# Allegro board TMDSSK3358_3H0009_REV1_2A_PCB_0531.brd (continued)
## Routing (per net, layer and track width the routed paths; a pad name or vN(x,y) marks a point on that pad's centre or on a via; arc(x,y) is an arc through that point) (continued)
DDR_BA2: length 43
  TOP w0.14: v2(77.12,11.96) 76.92,11.96 76.77,11.81 76.77,11.61 77.04,11.33 77.17,11.33 77.4,11.56 77.6,11.56 77.83,11.33 78.01,11.33 78.29,11.61 78.47,11.61 78.75,11.33 81.77,11.33 82.2,10.9 82.4,10.9 82.53,11.02 82.53,11.48 82.68,11.63 RP5.8
  LY6_SIG2 w0.127: v2(80.42,25.35) 81.21,24.56 81.43,24.56 83.48,22.52 83.48,19.12 84.28,18.31 84.28,13.57 80.83,10.12 78.63,10.12 78.29,9.78 78.29,8.59 77.29,7.59 76.36,7.59 76.21,7.44 75.34,7.44 75.12,7.66 75.12,8.16 75.36,8.4 75.68,8.4 75.91,8.63 75.91,9.89 76.29,10.27 76.29,11.14 v2(77.12,11.96)
  BOTTOM w0.14: U26.B3 79.91,27.44 79.91,25.85 v2(80.42,25.35) ; v2(77.12,11.96) 77.12,11.98 77.13,11.98 U32.M3
DDR_CASN: length 41.6
  TOP w0.14: v2(75.51,12.79) 75.51,12.48 76.97,11.02 81.64,11.02 82.12,10.54 RP6.1
  LY3_SIG1 w0.127: v2(76.34,25.4) 76.34,26.47 76.51,26.64 77.27,26.64 77.43,26.49 77.43,26.26 77.25,26.09 77.04,26.09 76.87,25.91 76.87,25.65 77.27,25.25 77.27,25.02 77.04,24.79 77.04,24.56 77.25,24.36 77.81,24.36 78.01,24.16 78.01,23.88 77.86,23.73 76.94,23.73 76.79,23.58 76.79,23.37 76.94,23.22 77.86,23.22 78.01,23.07 78.01,22.86 77.86,22.71 76.94,22.71 76.79,22.56 76.79,22.35 76.94,22.21 77.86,22.21 78.01,22.06 78.01,21.85 77.86,21.7 77.6,21.7 77.45,21.55 77.45,21.34 77.6,21.19 77.86,21.19 78.01,21.04 78.01,20.52 77.78,20.29 77.1,20.29 76.9,20.09 76.9,19.29 77.04,19.14 77.66,19.14 77.81,18.99 77.81,18.78 77.66,18.63 77.04,18.63 76.9,18.48 76.9,18.27 77.04,18.12 77.35,18.12 77.5,17.97 77.5,17.76 77.35,17.61 77.07,17.61 76.92,17.46 76.92,16.36 76.77,16.21 76.35,16.21 76.18,16.04 76.18,15.77 76.31,15.64 77.97,15.64 78.12,15.48 78.12,15.29 77.96,15.13 76.27,15.13 76.11,14.97 76.11,14.76 76.26,14.62 76.9,14.62 77.04,14.47 77.04,13.41 76.82,13.19 75.91,13.19 v2(75.51,12.79)
  BOTTOM w0.14: U32.K3 v2(75.51,12.79) ; v2(76.34,25.4) U26.F1
DDR_CKE: length 47
  LY3_SIG1 w0.127: v2(75.51,7.99) 75.92,8.4 79.66,8.4 79.91,8.16 79.91,7.83 79.67,7.59 79.35,7.59 74.71,7.59 74.31,7.99 74.31,8.96 73.97,9.3 73.97,9.63 74.25,9.91 74.25,11.68 75.11,12.55 75.11,13.94 75.64,14.46 75.64,17.63 76.33,18.32 76.33,24.03 76.49,24.18 76.49,24.7 76.18,25.01 76.18,25.01 75.94,25.24 v2(75.94,27.41)
  BOTTOM w0.14: v2(75.51,7.99) U32.K9 74.89,7.37 74.89,6.84 75.52,6.2 82.45,6.2 84.33,8.08 84.33,8.42 84.9,8.99 RP7.1 84.96,7.97 R242.2 ; U26.G3 v2(75.94,27.41)
DDR_CLK: length 41.1
  TOP w0.127: v2(74.71,9.6) 74.36,9.6 74.23,9.73 74.23,10.11 74.43,10.31 74.86,10.31 74.99,10.44 74.99,11.68 74.73,11.94 74.23,11.94 74.12,11.83 74.12,10.82 73.87,10.57 73.18,10.57 72.59,11.16 71.62,11.16 R89.1
  LY3_SIG1 w0.127: v2(81.36,23.11) 81.18,23.29 81.18,24.41 81.36,24.59 82.1,24.59 82.76,23.93 82.76,22.86 82.58,22.68 81.89,22.68 81.59,22.38 81.59,20.72 81.87,20.45 82.37,20.45 82.52,20.3 82.52,18.61 82.97,18.16 82.97,17.41 82.52,16.96 82.52,16.55 82.97,16.1 82.97,15.91 82.52,15.46 82.52,15.07 82.97,14.63 82.97,13.67 80.24,10.95 75.69,10.95 74.99,10.24 74.99,9.87 v2(74.71,9.6)
  BOTTOM w0.127: U26.D2 78.28,26.67 78.28,26.36 78.28,26.36 78.28,26.07 78.28,25.26 78.63,24.9 79.76,24.9 80.74,23.92 80.74,23.73 v2(81.36,23.11) ; U32.J7 v2(74.71,9.6)
DDR_CLKN: length 41.1
  TOP w0.127: R88.1 71.35,11.81 71.75,11.41 72.69,11.41 73.29,10.82 73.76,10.82 73.87,10.93 73.87,11.94 74.12,12.19 74.83,12.19 75.24,11.79 75.24,9.87 v2(75.51,9.6)
  LY3_SIG1 w0.127: v2(75.51,9.6) 75.24,9.87 75.24,10.13 75.8,10.69 76,10.69 76.26,10.44 76.51,10.44 76.77,10.69 80.35,10.69 83.22,13.56 83.22,14.73 82.77,15.18 82.77,15.35 83.22,15.8 83.22,16.2 82.77,16.65 82.77,16.85 83.22,17.3 83.22,18.26 82.77,18.71 82.77,20.41 82.48,20.7 81.97,20.7 81.85,20.83 81.85,22.28 82,22.43 82.68,22.43 83.01,22.76 83.01,24.03 82.2,24.84 81.26,24.84 80.93,24.51 80.93,23.32 v2(80.73,23.11)
  BOTTOM w0.127: v2(80.73,23.11) 80.49,23.35 80.49,23.81 79.65,24.65 78.53,24.65 77.95,25.23 77.95,26.2 U26.D1 ; U32.K7 v2(75.51,9.6)
DDR_CSN: length 43.5
  TOP w0.14: v2(76.31,13.6) 76.31,14.48 76.9,15.07 78.65,15.07 79.03,15.44 80.17,15.44 80.9,14.71 RP5.2
  LY6_SIG2 w0.127: v2(75.14,26.61) 74.33,26.61 73.96,26.98 73.96,27.53 73.69,27.8 73.38,27.8 73.15,28.03 73.15,28.37 72.9,28.62 72.58,28.62 72.34,28.86 72.34,31.66 72.12,31.87 71.78,31.87 71.54,31.64 71.54,29.9 71.87,29.57 71.87,28.84 72.34,28.37 72.34,28.05 72.58,27.82 72.73,27.82 72.73,27.82 72.89,27.82 72.9,27.81 72.9,27.81 73.16,27.55 73.16,26.73 73.37,26.52 73.77,26.52 73.96,26.34 73.96,26.1 73.78,25.92 72.94,25.92 72.73,25.7 72.73,25.17 72.89,25 73.37,25 73.52,24.86 73.52,24.19 73.67,24.04 73.84,24.04 74,23.88 74,23.52 73.54,23.05 73.54,22.32 73.67,22.19 73.91,22.19 74.12,22.41 74.12,22.92 74.29,23.09 75.15,23.09 75.36,22.89 75.36,22.39 74.4,21.44 74.4,18.72 75.31,17.81 75.45,17.67 75.45,16.42 76.05,15.82 76.05,15.34 76.31,15.08 v2(76.31,13.6)
  BOTTOM w0.14: U26.H2 v2(75.14,26.61) ; U32.L2 v2(76.31,13.6)
DDR_D0: length 29.8
  LY6_SIG2 w0.127: v2(71.14,27.41) 71.2,27.41 71.67,26.94 71.67,25.72 71.99,25.4 71.99,24.92 71.43,24.36 71.43,23.75 71.82,23.36 72.37,23.36 72.59,23.14 72.59,17.95 73.67,16.87 73.67,15.64 74.29,15.02 74.29,11.22 73.15,10.07 73.15,9.55 73.52,9.17 73.52,8.62 74.33,7.81 74.33,6.45 73.93,6.05 72.96,6.05 72.7,6.31 72.7,7.47 73.11,7.89 v2(73.11,8.8)
  BOTTOM w0.14: U26.M3 v2(71.14,27.41) ; U32.H8 v2(73.11,8.8)
DDR_D1: length 29.9
  LY6_SIG2 w0.127: v2(73.81,10.08) 73.81,9.44 73.99,9.26 74.17,9.26 74.32,9.41 74.32,9.87 74.52,10.08 74.88,10.08 75.07,10.27 75.07,10.52 74.91,10.69 74.78,10.69 74.63,10.83 74.63,11.04 74.79,11.19 75.36,11.19 75.5,11.34 75.5,11.55 75.35,11.7 74.82,11.7 74.67,11.85 74.67,12.06 74.83,12.21 74.97,12.21 75.11,12.36 75.11,14.92 74.54,15.49 74.32,15.71 74.18,15.85 74.18,16.69 74.18,17.08 73.13,18.13 73.13,18.19 73.13,19.25 73.13,19.25 73.13,24.05 72.33,24.85 72.33,25.57 72.1,25.79 72.1,26.98 72.33,27.2 72.33,27.58 72.1,27.81 72.08,27.81 72.07,27.82 70.89,27.82 70.74,27.96 70.74,29.18 70.99,29.42 71.33,29.42 71.54,29.2 71.54,28.61 v2(71.14,28.21)
  BOTTOM w0.14: U32.H7 73.51,9.8 73.8,10.08 v2(73.81,10.08) ; U26.M4 v2(71.14,28.21)
DDR_D2: length 29.7
  LY6_SIG2 w0.127: v2(70.74,25.27) 70.74,22.69 71.1,22.33 71.31,22.33 71.45,22.18 71.45,21.97 71.31,21.82 71.11,21.82 70.96,21.67 70.96,21.41 71.08,21.29 71.31,21.29 71.45,21.14 71.45,20.93 71.31,20.79 71.11,20.79 70.96,20.64 70.96,20.43 71.11,20.28 71.31,20.28 71.45,20.13 71.45,19.92 71.31,19.77 71.11,19.77 70.96,19.62 70.96,19.41 71.11,19.26 71.31,19.26 71.45,19.11 71.45,18.9 71.31,18.75 71.11,18.75 70.96,18.6 70.96,18.39 71.11,18.25 71.28,18.25 71.43,18.1 71.43,17.89 71.28,17.74 71.11,17.74 70.96,17.59 70.96,16.96 70.96,16.96 70.96,16.29 71.11,16.14 72.48,16.14 72.62,16 72.62,15.79 72.48,15.64 71.11,15.64 70.82,15.35 70.82,14.78 71.14,14.47 71.48,14.47 71.62,14.62 71.62,15.01 71.77,15.16 71.98,15.16 72.13,15.01 72.13,14.62 72.32,14.43 72.51,14.43 72.9,14.82 73.25,14.82 73.52,14.55 73.52,14.16 73.35,13.99 72.89,13.99 72.71,13.81 72.71,13.25 72.53,13.07 71.53,13.07 71.2,12.74 71.2,12.43 71.4,12.24 72.89,12.24 73.14,11.99 73.35,11.99 73.48,12.11 73.48,12.43 v2(73.11,12.79)
  BOTTOM w0.14: v2(70.74,25.27) U26.N1 ; U32.H3 v2(73.11,12.79)
DDR_D3: length 29.9
  LY6_SIG2 w0.127: v2(69.65,23.67) 69.65,23.32 67.77,21.44 67.77,21.23 67.94,21.06 67.94,20.85 67.79,20.7 67.58,20.7 67.41,20.87 67.2,20.87 67.05,20.72 67.05,20.51 67.67,19.89 67.67,19.68 67.53,19.53 67.31,19.53 66.69,20.15 66.48,20.15 66.3,19.97 66.3,18.89 66.43,18.76 67.62,18.76 67.76,18.62 67.76,18.41 67.62,18.26 66.43,18.26 66.3,18.13 66.3,17.72 67.13,16.88 67.62,16.88 67.77,16.74 67.77,16.53 67.62,16.38 67.2,16.38 67.05,16.23 67.05,16.02 67.2,15.87 67.62,15.87 67.77,15.72 67.77,15.51 67.62,15.36 67.2,15.36 67.05,15.21 67.05,14.59 67.26,14.38 67.88,14.38 68.03,14.23 68.03,14.02 67.88,13.87 67.16,13.87 67.01,13.72 67.01,13.41 68.24,12.18 70.1,12.18 v2(70.71,12.79)
  BOTTOM w0.102: U26.N2 70.35,26.62 70.35,24.37 v2(69.65,23.67)
  BOTTOM w0.14: v2(70.71,12.79) U32.E3
DDR_D4: length 29.8
  LY6_SIG2 w0.127: v2(70.34,27.41) 70.34,25.09 70.44,24.99 70.44,20.39 70.3,20.26 69.1,20.26 68.96,20.11 68.96,19.9 69.11,19.75 70.3,19.75 70.45,19.6 70.45,19.39 70.3,19.24 69.02,19.24 68.9,19.12 68.9,18.91 69.08,18.73 70.3,18.73 70.45,18.58 70.45,18.37 70.3,18.22 69.02,18.22 68.9,18.1 68.9,17.89 69.08,17.72 70.3,17.72 70.45,17.57 70.45,17.31 70.28,17.14 69.82,17.14 69.62,16.94 69.62,16.25 69.24,15.87 69.24,14.25 69.47,14.02 69.7,14.02 69.85,14.17 69.85,15.64 70,15.79 70.21,15.79 70.35,15.64 70.35,14.17 70.5,14.02 71.89,14.02 v2(72.31,13.6)
  BOTTOM w0.14: U32.G2 v2(72.31,13.6) ; U26.N3 v2(70.34,27.41)
DDR_D5: length 29.7
  LY6_SIG2 w0.127: v2(70.34,28.21) 70.34,28.78 70.08,29.03 70.08,29.36 70.72,30 70.72,31.29 70.59,31.42 70.16,31.42 69.75,31.01 69.38,31.01 69.15,30.78 69.15,30.76 69.14,30.76 69.14,28.85 69.38,28.62 69.69,28.62 69.93,28.38 69.93,28.32 69.93,26.82 70.06,26.7 70.06,22.73 69.27,21.94 69.27,21.73 69.67,21.33 69.67,21.12 69.52,20.98 69.31,20.98 68.91,21.37 68.7,21.37 68.5,21.17 68.5,20.66 68.3,20.46 68.3,15.12 68.71,14.7 68.71,13.43 68.7,13.43 68.93,13.2 71.12,13.2 v2(71.51,13.6)
  BOTTOM w0.14: U32.F2 v2(71.51,13.6) ; U26.N4 v2(70.34,28.21)
DDR_D6: length 29.7
  LY6_SIG2 w0.127: v2(69.54,27.41) 69.54,26.85 68.14,25.45 68.14,24.69 63.07,19.63 63.07,13.93 66.14,10.87 66.81,10.87 67.81,9.87 70.18,9.87 70.62,10.31 71.79,10.31 72.19,9.91 72.19,9.53 71.99,9.32 71.79,9.32 v2(71.51,9.6)
  BOTTOM w0.14: U32.F7 v2(71.51,9.6) ; U26.P3 v2(69.54,27.41)
DDR_D7: length 30
  LY6_SIG2 w0.127: v2(69.54,28.21) 69.14,27.82 69.14,27.18 67.73,25.76 67.73,25 62.57,19.84 62.57,13.51 66.77,9.31 69.5,9.31 70.81,7.99 v2(71.51,7.99)
  BOTTOM w0.14: U32.F8 v2(71.51,7.99) ; U26.P4 v2(69.54,28.21)
DDR_D8: length 29.8
  LY3_SIG1 w0.127: v2(69.11,12.79) 69.11,11.77 70.35,10.53 70.35,10.16 69.73,9.55 69.73,8.64 69.34,8.25 69.34,7.86 69.73,7.47 72.62,7.47 73.52,8.36 73.52,9.06 73.38,9.2 73.38,10.26 73.89,10.77 73.89,15.19 73.82,15.27 73.82,18.54 74.49,19.21 74.49,24.85 v2(73.94,25.4)
  BOTTOM w0.14: v2(73.94,25.4) U26.J1 ; U32.C3 v2(69.11,12.79)
DDR_D9: length 30.2
  LY3_SIG1 w0.127: v2(73.14,25.4) 72.64,25.4 71.23,23.99 71.23,22.16 70.94,21.87 70.94,20.45 71.18,20.2 71.18,19.85 71.03,19.7 70.82,19.7 70.57,19.95 70.36,19.95 70.21,19.8 70.21,19.59 70.46,19.34 70.46,19.13 70.31,18.98 70.1,18.98 69.85,19.23 69.64,19.23 69.49,19.08 69.49,18.87 69.74,18.62 69.74,18.41 69.5,18.17 68.49,18.17 66.76,16.43 66.76,14.4 66.62,14.27 66.02,14.27 65.87,14.12 65.87,13.91 66.02,13.76 66.62,13.76 66.77,13.61 66.77,13.4 66.62,13.25 66.02,13.25 65.87,13.11 65.87,12.89 66.02,12.75 66.62,12.75 66.76,12.61 66.76,11.91 67.67,11 67.67,10.7 67.49,10.51 67.21,10.51 v1(65.32,12.39)
  BOTTOM w0.14: v1(65.32,12.39) U32.A3 ; v2(73.14,25.4) U26.K1
DDR_D10: length 30.2
  LY3_SIG1 w0.127: v2(72.74,26.61) 72.74,25.89 70.8,23.95 70.8,22.96 69.4,21.56 69.4,20.79 69.79,20.39 69.79,20.18 69.64,20.04 69.43,20.04 68.97,20.49 68.76,20.49 68.61,20.35 68.61,20.13 69.07,19.68 69.07,19.47 68.92,19.32 68.71,19.32 68.25,19.78 68.04,19.78 67.9,19.63 67.9,19.42 68.35,18.96 68.35,18.75 68.21,18.6 68,18.6 67.54,19.06 67.33,19.06 67.18,18.91 67.18,18.7 67.64,18.24 67.64,18.03 67.49,17.88 67.28,17.88 66.82,18.34 66.61,18.34 66.46,18.19 66.46,17.98 66.92,17.52 66.92,17.31 66.77,17.16 66.56,17.16 66.1,17.62 65.89,17.62 65.32,17.05 65.32,16.75 65.47,16.6 66.1,16.6 66.25,16.45 66.25,16.24 66.1,16.09 65.47,16.09 65.32,15.95 65.32,15.74 65.47,15.59 66.1,15.59 66.25,15.44 66.25,15.23 66.1,15.08 65.47,15.08 65.32,14.93 v1(65.32,13.46)
  BOTTOM w0.14: v1(65.32,13.46) 66.48,13.46 66.75,13.2 U32.A2 ; U26.K2 v2(72.74,26.61)
DDR_D11: length 29.9
  LY3_SIG1 w0.127: v2(72.74,27.41) 72.24,26.92 72.24,26.46 71.53,25.74 70.53,25.74 70.16,25.37 70.16,25.17 69.12,24.13 68.5,24.13 65.58,21.21 64.95,20.58 64.95,19.9 65.11,19.74 65.33,19.74 65.54,19.53 65.54,19.14 63.76,17.36 63.76,12.34 66.45,9.65 69.17,9.65 v2(69.91,10.4)
  BOTTOM w0.14: U32.D7 69.91,9.6 v2(69.91,10.4) ; U26.K3 v2(72.74,27.41)
DDR_D12: length 30.3
  LY3_SIG1 w0.127: v2(72.74,28.21) 72.74,28 73.53,27.21 73.53,25.56 73.53,25.56 73.53,25.24 73.53,25.03 73.34,24.84 73.34,19.49 72.7,18.85 72.7,18.39 71.9,17.59 71.9,16.57 72.72,15.75 72.72,12.49 72.52,12.28 72.18,12.28 71.96,12.5 71.96,12.95 71.73,13.18 71.45,13.18 71.22,12.95 71.22,11.83 71.66,11.39 72.56,11.39 72.76,11.19 72.76,10.99 72.56,10.79 72.04,10.79 71.91,10.66 71.91,10.33 71.74,10.16 71.41,10.16 71.18,10.39 71.18,11.01 70.32,11.87 70.32,12.95 70.08,13.19 69.75,13.19 69.75,13.19 69.52,13.19 v2(69.11,13.6)
  BOTTOM w0.14: U32.C2 v2(69.11,13.6) ; U26.K4 v2(72.74,28.21)
DDR_D13: length 29.9
  LY3_SIG1 w0.127: v2(71.94,27.41) 71.62,27.09 71.62,26.39 71.35,26.13 69.63,26.13 69.1,25.6 69.1,24.85 68.83,24.58 68.23,24.58 63.26,19.6 63.26,19.28 63.4,19.13 64.23,19.13 64.37,18.99 64.37,18.78 64.22,18.62 63.4,18.62 63.26,18.47 63.26,12.13 66.81,8.57 67.5,8.57 67.72,8.8 v2(68.31,8.8)
  BOTTOM w0.14: U32.B8 v2(68.31,8.8) ; U26.L3 v2(71.94,27.41)
DDR_D14: length 30.3
  LY3_SIG1 w0.127: v2(71.94,28.21) 71.54,27.82 70.99,27.82 70.74,27.58 70.74,27.15 70.21,26.62 69.55,26.62 62.66,19.72 62.66,11.94 66.44,8.16 68.47,8.16 v2(69.11,8.8)
  BOTTOM w0.14: U32.C8 v2(69.11,8.8) ; U26.L4 v2(71.94,28.21)
DDR_D15: length 30.4
  LY3_SIG1 w0.127: v2(71.54,25.27) 71,24.74 70.5,24.74 70.15,24.39 70.15,23.31 69.51,22.67 69.3,22.67 68.62,23.34 68.43,23.34 68.28,23.19 68.28,22.97 68.94,22.31 68.94,22.1 68.79,21.95 68.58,21.95 67.9,22.62 67.71,22.62 67.56,22.47 67.56,22.25 68.22,21.59 68.22,21.38 68.07,21.23 67.86,21.23 67.19,21.9 66.99,21.9 66.84,21.76 66.84,21.53 67.5,20.87 67.5,20.66 67.35,20.51 67.14,20.51 66.52,21.13 66.3,21.13 66.15,20.98 66.15,20.79 66.78,20.15 66.78,19.66 64.82,17.69 64.82,12.08 v1(66.58,10.32)
  BOTTOM w0.14: U32.A7 66.96,9.2 66.58,9.57 v1(66.58,10.32) ; v2(71.54,25.27) U26.M1
DDR_DQM0: length 29.9
  LY6_SIG2 w0.127: v2(71.14,26.61) 71.15,26.6 71.15,23.48 71.96,22.66 71.96,17.86 73.16,16.66 73.16,15.47 73.9,14.73 73.9,11.4 72.71,10.21 72.71,8.17 72.29,7.76 72.29,6.92 71.71,6.34 70.51,6.34 70.22,6.62 70.22,7.22 70.46,7.46 71.62,7.46 71.91,7.75 71.91,7.83 71.91,7.83 71.91,8.16 71.91,8.16 71.91,8.4 v2(70.71,9.6)
  BOTTOM w0.14: U32.E7 v2(70.71,9.6) ; U26.M2 v2(71.14,26.61)
DDR_DQM1: length 30.1
  LY3_SIG1 w0.127: v2(73.94,24.57) 73.94,19.38 73.31,18.75 73.31,14.97 73.54,14.74 73.54,10.9 72.72,10.08 72.72,8.25 72.45,7.98 72.09,7.98 71.84,8.23 71.84,8.56 71.61,8.79 71.41,8.79 71.11,8.5 71.11,8.17 70.9,7.95 70.52,7.95 70.29,8.18 70.29,8.92 70.32,8.95 70.32,8.96 70.55,9.19 70.56,9.19 70.57,9.2 70.88,9.2 71.11,9.43 71.11,9.87 70.77,10.21 70.77,10.73 69.55,11.95 69.55,12.43 v2(69.91,12.79)
  BOTTOM w0.102: U26.J2 74.41,26.54 74.41,25.04 v2(73.94,24.57)
  BOTTOM w0.14: U32.D3 v2(69.91,12.79)
DDR_DQS0: length 30.3
  LY6_SIG2 w0.127: v2(71.91,11.81) 72.19,11.53 72.19,11.37 72.06,11.25 67.63,11.25 66.07,12.8 66.07,15.04 65.74,15.37 65.3,15.37 65.06,15.61 65.06,15.82 65.2,15.97 65.77,15.97 66.07,16.27 66.07,16.82 65.66,17.23 64.32,17.23 64.17,17.38 64.17,17.59 64.32,17.74 64.96,17.74 65.26,18.04 65.26,18.46 64.96,18.76 64.26,18.76 64.12,18.9 64.12,19.22 68.89,23.99 68.89,24.66 69.03,24.8 69.03,25.62 69.22,25.82 69.51,25.82 69.7,25.63 69.7,25.3 v2(69.51,25.1)
  BOTTOM w0.127: v2(71.91,11.81) U32.F3 ; v2(69.51,25.1) 69.94,25.53 U26.P1
DDR_DQS1: length 30.3
  LY3_SIG1 w0.127: v2(69.11,10.4) 68.82,10.69 68.82,11.14 67.56,12.39 67.56,13.83 67.75,14.02 71.64,14.02 72.02,14.4 72.02,15.36 71.3,16.08 69.94,16.08 69.02,15.16 68.46,15.16 68.04,15.58 68.04,16.28 68.91,17.15 69.71,17.15 69.71,17.15 69.92,17.15 72.2,19.43 72.2,20.63 72.09,20.73 72.09,23.37 72.19,23.47 72.43,23.47 72.56,23.33 72.81,23.33 72.93,23.46 72.93,23.7 v2(72.68,23.95)
  BOTTOM w0.127: v2(72.68,23.95) 72.68,23.98 72.38,24.27 72.38,25.74 72.34,25.78 U26.L1 ; v2(69.11,10.4) 68.89,10.17 68.89,9.9 69.24,9.55 69.24,9.32 69.37,9.2 U32.C7
DDR_DQSN0: length 30.3
  LY6_SIG2 w0.127: v2(68.63,25.05) 68.63,24.1 63.86,19.33 63.86,18.8 64.16,18.5 64.86,18.5 65,18.35 65,18.14 64.86,17.99 64.21,17.99 63.91,17.7 63.91,17.28 64.21,16.98 65.55,16.98 65.82,16.71 65.82,16.37 65.67,16.22 65.1,16.22 64.8,15.93 64.8,15.51 65.19,15.11 65.64,15.11 65.82,14.93 65.82,12.7 67.52,10.99 72.17,10.99 72.44,11.27 72.44,11.53 v2(72.71,11.81)
  BOTTOM w0.127: U32.G3 v2(72.71,11.81) ; v2(68.63,25.05) 69.55,25.97 69.55,26.66 69.9,27.01 U26.P2
DDR_DQSN1: length 30.3
  LY3_SIG1 w0.127: v2(71.84,23.98) 71.84,20.63 71.94,20.52 71.94,19.53 69.81,17.4 68.81,17.4 67.78,16.38 67.78,15.47 68.35,14.9 69.12,14.9 70.05,15.82 71.2,15.82 71.76,15.26 71.76,14.51 71.53,14.27 67.65,14.27 67.31,13.94 67.31,12.29 67.4,12.2 68.57,11.03 68.57,10.65 v2(68.31,10.4)
  BOTTOM w0.127: v2(71.84,23.98) 72.13,24.27 72.13,25.58 71.99,25.72 71.99,26.66 U26.L2 ; v2(68.31,10.4) 68.64,10.07 68.64,9.8 68.99,9.45 68.99,9.32 68.86,9.2 U32.B7
DDR_ODT: length 42
  TOP w0.14: RP5.1 80.93,15.29 80.27,15.95 79.05,15.95 78.54,15.44 75.62,15.44 v2(74.69,14.51)
  LY3_SIG1 w0.127: v2(75.54,25.5) 75.54,26.81 75.33,27.02 74.98,27.02 74.75,27.25 74.75,28.89 75.52,29.66 75.52,30.4 75.29,30.63 74.91,30.63 74.73,30.45 74.73,29.65 74.49,29.41 74.12,29.41 73.88,29.65 73.88,30.1 73.76,30.22 72.55,30.22 72.16,30.61 71.73,30.61 71.54,30.42 71.54,29.25 71.74,29.05 72.08,29.05 72.44,29.41 73.37,29.41 73.95,28.83 73.95,28.04 74.38,27.61 74.38,26.03 75.52,24.89 75.52,24.09 75.83,23.79 75.83,18.66 75.11,17.95 75.11,14.93 v2(74.69,14.51)
  BOTTOM w0.14: v2(74.69,14.51) 75.11,14.08 U32.K1 ; U26.G1 v2(75.54,25.5)
DDR_RASN: length 42.5
  TOP w0.14: RP6.2 82.25,9.96 81.51,10.69 76.82,10.69 v2(74.71,12.79)
  LY3_SIG1 w0.127: v2(74.71,12.79) 74.29,13.22 74.29,14.89 74.58,15.18 74.58,18.22 75.28,18.92 75.28,23.47 74.93,23.82 74.93,24.98 74.02,25.89 74.02,27.48 73.7,27.8 73.38,27.8 73.15,28.03 73.15,28.5 73.03,28.62 70.7,28.62 70.24,29.08 70.24,30.68 70.57,31.02 76.13,31.02 76.34,30.8 76.34,29.6 76.16,29.42 75.78,29.42 75.52,29.16 75.52,28.63 v2(75.94,28.21)
  BOTTOM w0.14: v2(75.94,28.21) U26.G4 ; U32.J3 v2(74.71,12.79)
DDR_RESETN: length 45.5
  LY6_SIG2 w0.127: v2(76.04,24.59) 76.04,24.37 75.88,24.21 75.71,24.21 75.57,24.35 75.57,24.85 75.93,25.22 75.93,25.55 76.29,25.91 76.56,25.91 76.75,25.71 76.75,24.55 76.46,24.25 76.46,23.98 76.69,23.75 76.69,21.43 76.03,20.78 76.03,19.25 76.16,19.13 76.51,19.13 76.64,19.26 76.64,20.29 76.74,20.4 77.07,20.4 77.16,20.31 77.16,17.54 77.31,17.39 77.57,17.39 77.7,17.51 77.7,19.43 77.85,19.58 78.06,19.58 78.21,19.43 78.21,17.94 78.35,17.79 79,17.79 79.15,17.64 79.15,17.43 79,17.28 78.14,17.28 77.94,17.08 77.94,16.45 78.11,16.28 78.46,16.28 78.6,16.14 78.6,15.84 78.46,15.7 78.01,15.7 77.7,15.39 77.7,14.61 77.86,14.45 78.09,14.45 78.21,14.58 78.21,15.08 78.34,15.2 78.57,15.2 78.7,15.07 78.7,14.2 78.9,13.99 79.74,13.99 79.86,13.87 80.38,13.87 v2(80.41,13.9)
  BOTTOM w0.102: v2(76.04,24.59) 76.04,25.11 75.93,25.22 75.93,26.62 U26.G2 ; v2(80.41,13.9) 80.42,13.91 80.42,13.91
  BOTTOM w0.14: 80.42,13.91 79.91,13.4 U32.T2 ; v2(80.41,13.9) 80.41,15.05 80.88,15.52 83.41,15.52 83.83,15.95 83.83,16.84 83.96,16.96 84.34,16.96 84.47,16.84 84.47,14.27 R241.1 85.36,14.56 R237.2
DDR_VREF: length 115.8
  TOP w0.254: C187.1 91.42,2.3 U14.6
  TOP w0.381: 80.07,0.96 80.1,0.94 85.36,0.94 85.69,1.27 v1(85.69,1.93) 85.75,1.87 86.23,1.87 86.24,1.88 87.22,0.89 91.82,0.89 C187.1 ; v2(73.11,14.39) 73.58,14.86 C145.1 ; C125.1 74.4,28.15 v2(74.34,28.21)
  TOP w0.508: v2(77.11,7.99) 76.71,7.99 76.41,7.7 76.41,6.96 76.84,6.53
  TOP w0.635: 76.84,6.53 76.84,5.89 ; 76.84,5.89 76.84,5.79 77.66,4.97 77.66,2.05 78.75,0.96 80.07,0.96 ; 76.84,5.89 75.83,4.88 68.46,4.88 65.91,7.43 65.91,11.32 66.63,12.04 66.63,12.91 67.55,13.83 67.59,13.87 67.68,13.92 67.72,13.94 68.33,14.55 69.37,14.55 69.66,14.84 72.66,14.84 v2(73.11,14.39) ; v1(97.67,22.63) 97.66,22.64 v1(97.66,23.37) 97.66,24.26 95.61,26.31 94.51,26.31 92.18,23.98 87.53,23.98 87.45,24.05 80.74,24.05 79.47,22.78 78.37,22.78 77.73,23.42 76.08,23.42 74.86,24.64 74.86,25.55 74.4,26.01 C125.1
  BOTTOM w0.305: U26.J4 v2(74.34,28.21)
  BOTTOM w0.381: 73.4,14.9 73.11,14.62 v2(73.11,14.39) U32.H1 ; U32.M8 v2(77.11,7.99) ; v1(85.69,1.93) 85.69,2.38 85.47,2.6 TP25.1
  BOTTOM w0.635: v1(97.66,23.37) 97.67,23.36 v1(97.67,22.63) 96.81,21.77 89.45,21.77 87.97,20.29 87.97,20.17 87.25,19.44 79.87,19.44 78.49,18.06 75.52,18.06 73.83,16.37 73.83,15.34 73.4,14.9
DDR_VTT_EN: length 3.3
  TOP w0.14: v1(91.54,2.8) U14.7
  BOTTOM w0.14: R243.2 R245.1 91.07,3.25 91.52,2.8 v1(91.54,2.8)
DDR_WEN: length 41.7
  TOP w0.14: v2(76.31,12.79) 76.05,12.79 75.95,12.69 75.95,12.55 76.36,12.14 76.61,12.14 76.87,12.4 78.17,12.4 78.47,12.7 80.85,12.7 81.13,12.42 81.82,12.42 82.11,12.71 RP5.6
  LY3_SIG1 w0.127: v2(79.14,27.41) 78.93,27.41 78.52,27 78.04,27 77.81,26.77 77.81,26.14 77.96,25.98 77.96,24.76 78.14,24.58 79.05,24.58 79.23,24.4 79.23,24.07 78.79,23.63 78.57,23.63 78.35,23.41 78.35,23.03 78.49,22.88 79.13,22.88 79.28,22.73 79.28,22.52 79.13,22.37 78.72,22.37 78.57,22.22 78.57,22.01 78.72,21.87 79.64,21.87 79.79,21.71 79.79,21.46 79.69,21.36 78.67,21.36 78.52,21.21 78.52,21 78.67,20.85 79.59,20.85 79.74,20.7 79.74,20.49 79.59,20.34 78.55,20.34 78.33,20.12 78.33,19.85 78.45,19.72 78.65,19.72 78.81,19.56 78.81,18.79 78.63,18.61 78.46,18.61 78.15,18.3 78.15,17.71 77.96,17.51 77.96,16.64 78.65,15.94 78.65,15.22 78.39,14.97 78.39,14.67 78.71,14.35 78.71,14.16 78.59,14.04 77.72,14.04 77.52,13.85 77.52,12.69 77.22,12.4 76.84,12.4 76.66,12.22 76.66,11.66 76.51,11.51 75.7,11.51 75.02,10.83 74.81,10.83 74.63,11.01 74.63,11.45 75.45,12.27 76.13,12.27 76.31,12.46 v2(76.31,12.79)
  BOTTOM w0.14: U26.B2 v2(79.14,27.41) ; U32.L3 v2(76.31,12.79)
DISEN: length 3.4
  TOP w0.14: J1.31 46.31,35.04 47.26,35.99 RP4.10
EMU2: length 5.8
  BOTTOM w0.14: J12.17 93.55,5.85 92.47,6.93 TP20.1
EMU3: length 7.7
  BOTTOM w0.14: J12.18 93.55,11.01 v1(93.43,11.12) 92.8,11.76 90.44,11.76 89.42,10.74 TP18.1
EMU4: length 5.5
  BOTTOM w0.14: J12.19 92.28,5.47 91.96,5.79 91.07,5.79 90.69,6.17 89.68,6.17 TP22.1
EMU_RSTN: length 6
  TOP w0.14: v1(95.47,1.98) 97.63,1.98 97.75,1.85 97.88,1.85 C183.1
  BOTTOM w0.14: J12.15 94.82,2.63 v1(95.47,1.98)
ETH1_INTN: length 7.8
  BOTTOM w0.14: R124.1 R123.2 R122.1 97.47,47 95.41,44.95 U23.5
ETH1_RBIAS: length 5.7
  BOTTOM w0.14: U23.9 97.01,43.95 97.45,44.39 97.45,44.39 98.03,44.98 100.26,44.98 100.53,44.7 R146.2
ETH1_RXCLK: length 5.5
  BOTTOM w0.14: U23.33 95.01,35.68 94.45,35.12 94.22,35.12 93.53,34.43 R209.2 93.89,33.04 93.97,33.04 R208.1
ETH1_RXD0: length 6.4
  BOTTOM w0.14: R204.1 98.86,33.4 98.79,33.47 98.31,33.47 98.24,33.4 R205.2 97.5,33.94 96.16,33.94 95.56,34.55 95.56,35.3 95.67,35.41 95.67,35.43 95.81,35.57 U23.31
ETH1_RXD1: length 8
  BOTTOM w0.14: U23.30 96.21,35.91 96.15,35.85 96.15,35.44 95.97,35.27 95.97,34.87 96.38,34.46 99.27,34.46 R203.1 R202.2
ETH1_RXD2: length 4.8
  TOP w0.14: v1(97.34,35.05) 98.04,34.35 R68.2 R69.1
  BOTTOM w0.14: U23.28 97.01,35.99 97.34,35.67 v1(97.34,35.05)
ETH1_RXD3: length 7
  TOP w0.14: R71.1 R70.2 99.88,34.99 v1(99.13,34.99)
  BOTTOM w0.14: v1(99.13,34.99) 98.3,34.99 97.8,35.48 97.8,35.67 97.41,36.06 U23.27
ETH1_RXDV: length 4.9
  BOTTOM w0.14: U23.32 95.41,35.64 95.34,35.57 95.34,35.55 95.04,35.24 95.04,34.05 R207.2 95.99,33.4 96,33.41 96.43,33.41 96.62,33.4 R206.1
ETH2_INTN: length 10.7
  TOP w0.14: v1(54.67,45.06) 54.29,45.06 54.29,45.06 51.93,45.06 51.55,45.44 51.55,47.34 51.37,47.53 R22.1 R21.1 R20.1
  BOTTOM w0.14: v1(54.67,45.06) 55.03,44.7 U24.5
ETH2_RBIAS: length 3.8
  BOTTOM w0.14: U24.9 56.63,43.38 56.55,43.46 56.55,44.38 57.13,44.96 R145.2
ETH2_RXCLK: length 5.5
  BOTTOM w0.14: U24.33 54.63,35.11 54.1,34.59 53.71,34.59 53.71,34.59 53.55,34.43 53.08,34.43 52.38,33.74 R199.2 R200.1
ETH2_RXD0: length 4.2
  BOTTOM w0.14: R195.1 R196.2 55.64,33.87 55.64,34.54 55.42,34.76 55.42,36.08 55.43,36.09 U24.31
ETH2_RXD1: length 4.9
  BOTTOM w0.14: U24.30 55.83,36.09 55.75,36.01 55.75,35.16 56.48,34.43 56.77,34.43 57.46,33.73 R194.1 R193.2
ETH2_RXD2: length 4.4
  TOP w0.14: v1(56.64,34.94) 56.13,34.43 R64.2 R65.1
  BOTTOM w0.14: U24.28 56.63,36.14 56.7,36.07 56.7,35.62 56.64,35.56 v1(56.64,34.94)
ETH2_RXD3: length 6.1
  TOP w0.14: v1(57.4,34.92) 57.4,34.29 58.04,33.66 R66.2 R67.1
  BOTTOM w0.14: v1(57.4,34.92) 57.4,35.59 57.03,35.96 57.03,36.15 57.03,36.15 U24.27
ETH2_RXDV: length 4.3
  BOTTOM w0.14: U24.32 55.03,34.98 54.41,34.36 R197.1 R198.2
ETH_MDIO_CLK: length 2.6
  BOTTOM w0.14: R147.1 52.25,43.43 52.86,42.83 U24.1
ETH_MDIO_DATA: length 3.4
  BOTTOM w0.14: U24.48 52.55,42.38 52.13,42.8 50.58,42.8 50.04,43.34 R148.1
ETH_RESETN: length 91.3
  TOP w0.14: v1(88.58,48.87) 84.64,48.87 84.16,48.39 84.16,47.32 84.99,46.48 84.99,45.69 85.35,45.34 U6.4 ; R47.1 v1(51.87,43.91) 48.19,47.59 v1(48.19,50.7) ; v1(93.6,45.34) 94.74,46.48 R26.2
  LY3_SIG1 w0.127: v1(48.19,50.7) 48.19,52.37 50.92,55.1 68.31,55.1 69.19,54.22 69.19,53.31 69.48,53.02 77.62,53.02 79.36,54.77 88.07,54.77 88.6,54.24 88.6,53.76 90.16,52.2 93.52,52.2 94.14,51.57 94.14,45.88 v1(93.6,45.34) 93.18,45.76 92.63,45.76 91.56,46.82 90.63,46.82 v1(88.58,48.87)
  BOTTOM w0.14: U23.2 94.21,43.33 93.4,44.14 93.4,45.14 v1(93.6,45.34) ; v1(51.87,43.91) 52.54,43.91 52.89,43.56 53.59,43.56 53.83,43.33 U24.2
ETHER2_D0N: length 22.9
  LY6_SIG2 w0.121: v1(57.96,44.39) 57.74,44.17 57.74,42.82 58.86,41.7 60.91,41.7 62.6,43.39 62.6,47.47 63.03,47.9 63.03,48.47 64.22,49.66 64.78,49.66 65.69,50.57 65.69,51.99 66.52,52.82 66.95,52.82 68,53.87 J7.10
  BOTTOM w0.102: U24.12 57.83,43.38 57.76,43.45 57.76,44.19 v1(57.96,44.39)
ETHER2_D0P: length 23.1
  LY6_SIG2 w0.121: J7.9 67.27,51.6 67.27,52.25 66.94,52.57 66.62,52.57 65.94,51.89 65.94,50.46 64.88,49.41 64.32,49.41 63.28,48.36 63.28,47.8 62.85,47.37 62.85,43.29 61.01,41.45 58.76,41.45 57.49,42.72 57.49,44.2 v1(57.3,44.39)
  BOTTOM w0.102: U24.11 57.43,43.38 57.49,43.45 57.49,44.2 v1(57.3,44.39)
ETHER2_D1N: length 17.8
  LY6_SIG2 w0.121: J7.8 64.77,52.91 64.32,52.91 63.15,51.74 63.15,50.01 60.7,47.56 60.7,43.01 60.45,42.76 60.03,42.76 59.86,42.93 59.86,43.07 v1(60.07,43.28)
  BOTTOM w0.102: v1(60.07,43.28) 59.88,43.09 59.88,41.57 59.52,41.21 59.11,41.21 59.05,41.15 U24.15
ETHER2_D1P: length 17.9
  LY6_SIG2 w0.121: v1(59.41,43.28) 59.61,43.08 59.61,42.82 59.92,42.51 60.55,42.51 60.95,42.91 60.95,47.45 63.4,49.9 63.4,51.64 64.42,52.66 64.64,52.66 64.9,52.4 64.9,51.77 J7.7
  BOTTOM w0.102: U24.14 59.03,41.55 59.11,41.48 59.41,41.48 59.61,41.68 59.61,43.07 v1(59.41,43.28)
ETHER2_D2N: length 23.4
  LY6_SIG2 w0.121: J7.6 62.45,53.13 61.88,53.13 60.61,51.86 60.61,50.9 60.49,50.77 55.3,45.59 55.3,43.46 58.75,40.02 60.7,40.02 v1(60.9,39.81)
  BOTTOM w0.102: v1(60.9,39.81) 60.7,40.02 59.33,40.02 59.26,39.95 U24.18
ETHER2_D2P: length 23.5
  LY6_SIG2 w0.121: v1(60.9,40.47) 60.69,40.27 58.85,40.27 55.55,43.57 55.55,45.49 60.86,50.79 60.86,51.76 61.98,52.88 62.44,52.88 62.62,52.7 62.62,52.48 61.92,51.78 J7.5
  BOTTOM w0.102: v1(60.9,40.47) 60.71,40.28 59.33,40.28 59.26,40.35 U24.17
ETHER2_D3N: length 26.5
  LY6_SIG2 w0.121: v1(60.47,38.46) 60.27,38.66 58.63,38.66 57.13,40.16 54.06,40.16 53.65,40.57 53.65,44.83 53.81,44.98 53.81,47.12 56.82,50.13 57.26,50.13 58.07,50.95 58.07,51.99 59.28,53.21 59.87,53.21 60.53,53.87 J7.4
  BOTTOM w0.102: v1(60.47,38.46) 60.29,38.64 59.84,38.64 59.66,38.82 59.33,38.82 59.26,38.75 U24.21
ETHER2_D3P: length 26.6
  LY6_SIG2 w0.121: J7.3 59.38,51.73 60.03,52.37 60.03,52.78 59.85,52.96 59.39,52.96 58.32,51.89 58.32,50.84 57.36,49.89 56.92,49.89 54.06,47.02 54.06,44.88 53.9,44.72 53.9,40.67 54.17,40.41 57.23,40.41 58.73,38.91 60.26,38.91 v1(60.47,39.12)
  BOTTOM w0.102: v1(60.47,39.12) 60.26,38.91 59.95,38.91 59.77,39.08 59.33,39.08 59.26,39.15 U24.20
ETHER_D0N: length 17.7
  LY6_SIG2 w0.121: J6.10 89.67,53.29 89.67,52.8 91.93,50.54 93.74,50.54 99.53,44.74 99.53,44.52 v1(99.74,44.31)
  BOTTOM w0.102: v1(99.74,44.31) 99.5,44.08 99.5,43.7 99.25,43.45 98.32,43.45 98.21,43.34 U23.12
ETHER_D0P: length 17.8
  LY6_SIG2 w0.121: J6.9 88.97,52.36 89.16,52.55 89.56,52.55 91.83,50.29 93.64,50.29 99.26,44.67 99.26,44.49 v1(99.08,44.31)
  BOTTOM w0.102: v1(99.08,44.31) 99.23,44.16 99.23,43.81 99.13,43.72 98.21,43.72 97.81,43.32 U23.11
ETHER_D1N: length 23.1
  LY6_SIG2 w0.121: v1(100.84,42.64) 100.62,42.86 100.62,43.09 100.35,43.35 99.17,43.35 93.22,49.3 89.13,49.3 87.84,50.6 87.84,52.15 87.03,52.96 87.03,53.19 J6.8
  BOTTOM w0.102: v1(100.84,42.64) 100.64,42.45 100.64,41.7 100.19,41.25 99.53,41.25 99.43,41.15 U23.15
ETHER_D1P: length 23
  LY6_SIG2 w0.121: v1(100.18,42.64) 100.37,42.83 100.37,42.99 100.25,43.11 99.07,43.11 93.12,49.05 89.03,49.05 87.59,50.49 87.59,52.04 86.88,52.76 86.59,52.76 86.43,52.59 J6.7
  BOTTOM w0.102: U23.14 99.42,41.55 99.46,41.51 100.08,41.51 100.37,41.81 100.37,42.45 v1(100.18,42.64)
ETHER_D2N: length 30
  LY6_SIG2 w0.121: v1(101.24,39.82) 101.03,40.03 100.52,40.03 99.39,41.16 97.76,42.79 97.26,42.79 92.73,47.33 88.96,47.33 86.49,49.79 83.27,49.79 82.6,50.46 82.6,51.76 84,53.16 84.46,53.16 J6.6
  BOTTOM w0.102: v1(101.24,39.82) 101.04,40.02 99.49,40.02 99.42,39.95 U23.18
ETHER_D2P: length 30.1
  LY6_SIG2 w0.121: v1(101.24,40.48) 101.04,40.29 100.61,40.29 99.49,41.41 97.86,43.04 97.36,43.04 92.83,47.57 89.06,47.57 86.59,50.04 83.37,50.04 82.85,50.56 82.85,51.66 84.11,52.91 84.35,52.91 84.64,52.63 84.64,52.07 J6.5
  BOTTOM w0.102: U23.17 99.43,40.35 99.49,40.28 101.04,40.28 v1(101.24,40.48)
ETHER_D3N: length 32.5
  LY6_SIG2 w0.121: v1(100.56,38.63) 100.38,38.82 99.52,38.82 99.03,39.31 99.03,40.02 97.26,41.79 96.06,41.79 92,45.84 87.16,45.84 84.65,48.35 84.46,48.53 81.95,48.53 81.08,49.4 80.04,50.44 80.04,52.25 80.92,53.13 81.89,53.13 J6.4
  BOTTOM w0.102: v1(100.56,38.63) 100.37,38.82 99.49,38.82 99.42,38.75 U23.21
ETHER_D3P: length 32.4
  LY6_SIG2 w0.121: v1(100.56,39.27) 100.36,39.07 99.63,39.07 99.28,39.41 99.28,40.12 97.36,42.04 96.16,42.04 92.11,46.09 87.26,46.09 84.83,48.52 84.57,48.78 82.06,48.78 81.19,49.65 80.29,50.55 80.29,52.15 81.02,52.88 81.77,52.88 81.95,52.7 81.95,52.27 81.35,51.68 J6.3
  BOTTOM w0.102: v1(100.56,39.27) 100.39,39.09 99.49,39.09 99.43,39.15 U23.20
EXP_PB_POWERON: length 51.7
  LY3_SIG1 w0.127: v1(112.78,34.07) 112.78,33.25 113.28,32.74 115.36,32.74 116.09,32.02 126.76,32.02 129.35,34.61 129.35,43.56 131.29,45.5 v1(131.29,53.97)
  BOTTOM w0.14: v1(112.78,34.07) 113.01,34.31 113.01,36.23 U25.33 ; SW5.3 131.29,60.61 132.72,59.18 132.72,58.04 131.29,56.61 SW5.4 v1(131.29,53.97) 131.19,53.97 R112.1
F_ADBUS0: length 2.8
  TOP w0.14: R75.2 v1(44.41,25.02)
  BOTTOM w0.14: U28.16 45.07,25.08 45.02,25.02 v1(44.41,25.02)
F_ADBUS1: length 2.8
  BOTTOM w0.14: R227.2 45.4,21.54 45.07,21.87 44.71,21.87 44.42,22.16 U28.17
F_ADBUS2: length 2.3
  BOTTOM w0.14: R228.2 44.25,21.64 43.92,21.97 U28.18
F_ADBUS3: length 2.1
  TOP w0.14: R79.2 v1(43.31,24.6)
  BOTTOM w0.14: v1(43.31,24.6) 43.42,24.49 U28.19
F_ADBUS4: length 2.5
  BOTTOM w0.14: U28.21 42.42,22.04 R229.2
F_ADBUS5: length 3.2
  TOP w0.14: R78.2 v1(39.62,25.11)
  BOTTOM w0.14: U28.26 39.92,24.81 v1(39.62,25.11)
F_ADBUS6: length 2.6
  BOTTOM w0.14: R230.2 41.42,22.19 U28.23
F_ADBUS7: length 3.3
  TOP w0.14: v1(38.23,25.15) R77.2
  BOTTOM w0.14: v1(38.23,25.15) 37.92,24.84 U28.30
F_EECS: length 15.3
  TOP w0.14: v1(43.92,27.65) 45.46,26.11 47.38,26.11 R76.2 48.47,23.86 47.88,23.27 U9.5
  BOTTOM w0.14: U28.63 v1(43.92,27.65)
F_EEDATA: length 20.6
  TOP w0.14: U9.3 48.83,20.65 48.4,21.08 R81.1 45.21,21.89 44.3,22.81 44.3,24.45 43.36,25.39 43.36,27.81 42.96,28.22 42.35,28.22 v1(42.07,27.94)
  BOTTOM w0.14: v1(42.07,27.94) 42.92,28.79 U28.61
F_EEDOUT: length 6.7
  TOP w0.14: R83.2 42.91,20.07 43.93,21.08 R81.2 44.71,20.57 46.81,20.57 46.93,20.45 U9.1
F_EESK: length 29.6
  TOP w0.14: v1(42.81,27.65) 42.07,26.91 42.07,23.29 40.93,22.15 40.93,20.68 R82.2 40.32,19.38 40.85,18.85 44.51,18.85 45.03,18.32 48.46,18.32 49.22,19.08 49.23,19.08 49.35,19.2 49.35,20.38 49.2,20.52 49.2,20.8 48.83,21.17 U9.4
  BOTTOM w0.14: v1(42.81,27.65) 43.42,28.26 U28.62
FT_DM: length 63.8
  LY3_SIG1 w0.127: v1(46.23,59.69) 45.9,59.36 43.08,59.36 41.69,57.96 41.69,56.67 39.07,54.05 36.55,54.05 33.92,51.43 32.16,51.43 26.54,45.81 26.54,43.13 27.91,41.77 27.91,40.43 28.32,40.02 28.87,40.02 29.1,39.79 29.1,38.93 29.61,38.41 29.61,38.41 29.61,36.21 33.83,31.99 33.83,31.05 35.23,29.65 35.23,27.98 36.58,26.62 37.22,26.62 37.29,26.54 v1(37.29,26.24)
  BOTTOM w0.127: v1(37.29,26.24) 37.47,26.41 37.47,26.87 37.77,27.18 44.15,27.18 44.5,27.53 44.5,29.06 44.9,29.46 45.42,29.46 45.53,29.58 U28.7 ; v1(46.23,59.69) 46.23,59.36 45.95,59.08 45.43,59.08 U16.28
FT_DP: length 63.9
  LY3_SIG1 w0.127: v1(37.95,26.24) 37.55,26.64 37.55,26.65 37.32,26.87 36.69,26.87 35.48,28.08 35.48,29.76 34.08,31.16 34.08,32.1 29.86,36.31 29.86,37.83 29.86,38.52 29.35,39.03 29.35,39.9 28.98,40.27 28.42,40.27 28.16,40.53 28.16,41.87 26.8,43.24 26.8,45.71 32.27,51.17 34.03,51.17 36.65,53.8 39.17,53.8 41.94,56.57 41.94,57.86 43.19,59.11 45.98,59.11 46.29,58.8 46.63,58.8 46.74,58.9 v1(46.74,59.18)
  BOTTOM w0.127: v1(46.74,59.18) 46.41,59.18 46.22,58.99 U16.1 ; v1(37.95,26.24) 37.95,26.31 37.72,26.54 37.72,26.77 37.88,26.92 44.25,26.92 44.76,27.43 44.76,28.96 45.01,29.21 45.39,29.21 45.52,29.08 U28.8
FT_REF: length 1.8
  BOTTOM w0.14: R214.2 47.61,29.84 47.37,30.08 U28.6
FT_RESETN: length 1.6
  BOTTOM w0.14: R221.1 47.34,26.04 47.3,26.08 U28.14
FT_SRESET: length 60.9
  TOP w0.14: v1(51.31,52.58) R16.2 50.55,54.31 50.25,54.61 49.22,54.61 49.04,54.43 U4.1 ; v1(41.46,24.51) 41.46,23.57 40.75,22.86 R78.1
  LY6_SIG2 w0.127: v1(41.46,24.51) 40.72,25.25 40.23,25.25 38.79,26.68 37.9,26.68 36.74,27.83 36.74,28.95 34.61,31.08 34.61,31.15 34.59,31.16 34.59,34.44 30.24,38.8 30.24,42.23 31.26,43.26 38.17,43.26 39.31,44.39 39.31,44.63 40.49,45.82 40.78,45.82 42.64,47.68 42.64,49.58 43.14,50.08 43.14,51.72 44.45,53.02 45.79,53.02 47.86,55.09 48.79,55.09 v1(51.31,52.58)
FT_SRESETB: length 2.3
  TOP w0.14: U5.6 40.44,51.18 40.32,51.05 R17.2
FT_SRESETN: length 4.9
  TOP w0.14: U5.1 45.71,51.18 45.95,50.94 47.49,50.94 47.74,51.18 U4.4
FT_VBUS: length 41.8
  TOP w0.381: U4.2 v1(48.39,54.65)
  LY6_SIG2 w0.381: v1(39.17,41.53) 39.18,41.54 39.18,42.77 39.97,43.56 47.99,43.56 48.5,44.06 48.5,44.67 47.97,45.21 45.04,45.21 43.29,46.96 43.29,48.68 45.23,50.62 46.75,50.62 48.39,52.26 v1(48.39,54.65)
  BOTTOM w0.254: 41.92,35.58 U28.59 ; 46.9,54.96 46.57,55.29 U16.7
  BOTTOM w0.381: R110.1 47.96,53.79 48.39,54.21 v1(48.39,54.65) 47.22,54.65 46.9,54.96 ; 41.92,35.58 41.92,37.33 40.85,38.4 40.85,39.85 v1(39.17,41.53)
GPIO_KEY1: length 130.5
  TOP w0.14: SW3.3 v1(131.15,30.23) SW3.4
  LY6_SIG2 w0.127: v2(67.56,42.24) 67.56,42.49 68.86,43.78 68.86,47.34 71.75,50.24 71.75,50.98 73,52.22 73,52.55 73.91,53.46 73.91,54.9 73.59,55.22 73.59,63.43 76.96,66.8 89.41,66.8 91.81,69.2 114.14,69.2 115.86,67.48 115.86,58.92 118.61,56.18 127.46,56.18 129.29,54.36 129.29,53.59 131.7,51.18 131.7,42.61 130.47,41.39 130.47,38.5 131.19,37.78 131.19,30.26 v1(131.15,30.23)
  BOTTOM w0.14: v1(131.15,30.23) C243.1 R215.2 ; U26.T17 67.97,39.38 67.97,41.84 v2(67.56,42.24)
GPIO_KEY2: length 102.2
  TOP w0.127: v2(68.74,30.61) 68.33,30.21 68.33,28.84 68.21,28.72
  TOP w0.14: v1(131.15,44.2) SW1.3 SW1.4 ; v1(95.92,24) 94.75,24 92.76,22.01 86.05,22.01 85.59,21.55 80.86,21.55 79.77,20.45 74.8,20.45 70.34,24.91 70.34,25.5 68.98,26.86 67.92,26.86 67.54,27.25 67.54,28.38 67.77,28.61 68.11,28.61 68.21,28.72
  LY3_SIG1 w0.127: v1(131.15,44.2) 131.15,41.37 130.62,40.83 130.62,34.6 127.07,31.06 113.3,31.06 112.41,30.17 112.41,27.97 108.65,24.21 100.16,24.21 99.04,25.32 95.39,25.32 95.28,25.44 94.91,25.44 94.65,25.18 94.65,24.81 95.45,24 v1(95.92,24)
  BOTTOM w0.14: U26.T7 v2(68.74,30.61) ; v1(131.15,44.2) 131.19,44.16 R165.2 C220.1
GPIO_KEY3: length 93.6
  TOP w0.14: SW2.4 v1(131.15,38.72) SW2.3 ; v1(95.09,24.99) 92.48,22.38 85.9,22.38 85.43,21.92 80.71,21.92 80.2,21.41 74.65,21.41 72.28,23.79 72.28,24.11 72,24.38 71.87,24.38 71.14,25.11 71.14,25.44 70.91,25.67 70.71,25.67 69.14,27.25 69.14,30.21 v2(69.54,30.61)
  LY3_SIG1 w0.127: v1(95.09,24.99) 98.46,24.99 99.64,23.81 110.87,23.81 111.37,23.31 113.42,23.31 114.06,23.95 114.06,25.6 112.79,26.87 112.79,29.15 113.52,29.89 128.44,29.89 131.15,32.6 v1(131.15,38.72)
  BOTTOM w0.14: C228.1 R172.2 131.26,38.61 v1(131.15,38.72) ; U26.R7 v2(69.54,30.61)
GPIO_KEY4: length 97.6
  TOP w0.14: v1(94.77,23.29) 93.13,21.64 86.2,21.64 85.74,21.18 83.19,21.18 81.01,21.18 79.92,20.09 69.5,20.09 69.25,20.34 69.25,24.28 69.91,24.94 69.91,25.27 68.66,26.52 67.39,26.52 67.08,26.82 67.08,28.96 v2(67.94,29.81) ; 131.06,19.05 131.15,19.14 SW4.4 ; 131.06,19.05 131.15,18.96 SW4.3 ; 131.06,19.05 v1(131.15,19.05)
  LY3_SIG1 w0.127: v1(94.77,23.29) 96.32,23.29 96.84,23.81 98.6,23.81 99.86,22.56 105.78,22.56 106.29,22.04 113.68,22.04 114.57,22.93 114.57,25.6 113.17,27 113.17,28.7 113.95,29.47 120.73,29.47 v1(131.15,19.05)
  BOTTOM w0.14: v1(131.15,19.05) R231.2 C263.1 ; U26.T6 v2(67.94,29.81)
HD_SPKRM: length 2.7
  BOTTOM w0.14: U31.22 38.08,7.99 38.2,7.88 38.2,6.41 TP21.1
HD_SPKRP: length 8.3
  TOP w0.14: C185.1 38.26,2.16 v1(38.18,2.24)
  BOTTOM w0.14: U31.23 37.58,7.75 37.68,7.66 37.68,5.05 38.18,4.54 v1(38.18,2.24)
HS_IND: length 4.2
  TOP w0.14: R14.2 40.06,53.34 v1(40.32,53.59)
  BOTTOM w0.14: v1(40.32,53.59) 40.32,55.37 40.74,55.79 U16.16
HS_SPKRM: length 5.7
  BOTTOM w0.14: TP24.1 39.24,7.58 39.58,7.92 U31.19
HS_SPKRP: length 26
  TOP w0.14: v1(56.45,1.8) 56.47,1.8 57.35,2.69 C181.1
  LY3_SIG1 w0.127: v1(56.45,1.8) 55.92,1.28 42.84,1.28 v1(41.51,2.62)
  BOTTOM w0.14: U31.18 40.08,7.68 39.76,7.37 39.76,4.24 41.51,2.49 v1(41.51,2.62)
HUB_BIAS: length 2.3
  BOTTOM w0.14: U16.26 44.32,60.83 44.45,60.96 R99.1
HUB_USBDM_UP: length 4.1
  BOTTOM w0.127: L1.2 39.41,59.43 39.56,59.28 39.56,58.91 40,58.47 40.58,58.47 40.94,58.82 41.61,58.82 41.81,58.62 41.87,58.57 41.87,58.37 41.79,58.29 U16.21
HUB_USBDP_UP: length 4.1
  BOTTOM w0.127: U16.22 42.32,58.95 42.17,58.8 41.99,58.8 41.71,59.08 40.83,59.08 40.47,58.72 40.11,58.72 39.82,59.01 39.82,59.43 39.94,59.55 L1.1
I2C_SCL_AUDIO: length 90.5
  LY3_SIG1 w0.127: v1(43.31,16.51) 44.25,16.51 45.16,15.6 45.58,15.6 45.79,15.81 49.26,15.81 51.55,13.52 51.55,13.15 53.79,10.92 53.79,7.47 53.86,7.39 56.84,4.42 57.26,4.42 57.76,4.42 59.74,2.44 59.96,2.22 76.99,2.22 77.56,2.79 82.46,2.79 82.95,3.28 90.67,3.28 91.4,4.01 101.99,4.01 104.18,6.19 104.18,10.61 104.92,11.35 104.92,13.91 103.08,15.75 99.86,15.75 v1(98.55,17.05)
  BOTTOM w0.14: U31.1 v1(43.31,16.51) ; v1(98.55,17.05) 97.59,17.05 R232.1
I2C_SDA_AUDIO: length 91.5
  LY3_SIG1 w0.127: v1(95.81,17.42) 95.85,17.46 96.58,17.46 98.8,15.24 102.57,15.24 104.53,13.28 104.53,11.72 103.85,11.03 103.85,6.46 101.78,4.39 91.31,4.39 90.53,3.61 82.56,3.61 82.07,3.12 77.43,3.12 77.38,3.08 76.89,2.59 63.5,2.59 62.97,3.11 59.79,3.11 57.97,4.93 57.06,4.93 54.24,7.74 54.24,11.18 52.06,13.36 52.06,13.91 49.01,16.95 48.19,16.95 47.81,16.58 45.84,16.58 v1(45.37,16.11)
  BOTTOM w0.14: v1(45.37,16.11) 44.57,15.31 44.57,15.08 43.96,14.46 U31.2 ; v1(95.81,17.42) 93.51,17.42 R233.1
JTAG_EMU0: length 111.8
  TOP w0.14: v1(91.2,8.3) 89.62,9.87 R90.2 89.73,10.49 v1(90.44,10.49)
  LY3_SIG1 w0.127: v1(39.2,19.51) 39.14,19.57 39.14,20.33 39.45,20.64 47.51,20.64 48.53,21.66 49.22,21.66 49.47,21.91 51.2,21.91 51.82,21.29 54.2,21.29 55.94,19.55 56.6,19.55 60.34,15.82 60.34,11.2 63.09,8.45 64.49,8.45 66.42,6.52 75.56,6.52 75.84,6.8 79.68,6.8 79.93,7.05 79.93,7.15 80.31,7.53 80.88,7.53 83.83,10.49 v1(90.44,10.49)
  LY6_SIG2 w0.127: v2(79.14,37.01) 79.53,37.01 80.22,36.32 80.22,32.54 81.39,31.37 82.28,31.37 82.77,30.87 82.77,30.14 86.55,26.36 88.15,26.36 90.36,24.15 90.36,20.33 91.07,19.61 91.07,16.42 90.79,16.14 90.79,15.32 92.2,13.91 92.2,12.25 v1(90.44,10.49)
  BOTTOM w0.14: U26.C14 v2(79.14,37.01) ; v1(91.2,8.3) 91.2,7.93 91.81,7.31 94.19,7.31 96.09,5.42 J12.13 ; v1(39.2,19.51) 39.76,19.51 R230.1
JTAG_EMU1: length 110.6
  TOP w0.14: R77.1 38.23,21.49 v1(39.58,20.14)
  LY3_SIG1 w0.127: v1(39.58,20.14) 39.74,20.31 48.94,20.31 49.59,20.96 54.06,20.96 55.83,19.2 56.19,19.2 57.87,17.51 57.87,12.55 58.55,11.87 58.95,11.87 63.44,7.38 64.34,7.38 65.53,6.18 75.74,6.18 76.07,6.52 80.56,6.52 84.01,9.97 84.2,9.97 90.61,9.97 91.23,10.59 91.23,10.99 92.2,11.97 92.2,14.69 v1(91.45,15.44) 89.91,16.98 89.91,24.13 88.07,25.97 87.04,25.97 86.73,25.97 85.05,27.66 85.05,27.78 82.36,30.47 82.06,30.47 81.71,30.82 81.71,36.87 v2(81.84,37.01)
  BOTTOM w0.14: U26.B14 79.93,37.01 v2(81.84,37.01) ; J12.14 96.09,11.44 95,12.54 95,13.38 94.15,14.23 92.66,14.23 v1(91.45,15.44) 91.52,15.51 R234.1
JTAG_TCK: length 184.3
  TOP w0.14: v1(45.42,23.16) 45.42,23.2 46.29,24.07 R75.1 ; R91.2 R92.2 95.97,11.55 95.43,12.09 90.48,12.09 89.96,12.62 89.96,15.04 92.01,17.09 92.01,18.27 92.34,18.61 92.94,18.61 94.34,20.01 95.09,20.01 95.12,19.99 98.34,19.99 100.08,21.72 100.08,27.05 97.85,29.28 97.85,29.55 92.2,35.2 88.47,35.2 87.49,34.22 85.12,34.22 84.8,34.53 84.47,34.53 v2(84.11,34.9)
  LY3_SIG1 w0.127: v1(45.42,23.16) 43.78,21.53 39.4,21.53 38.63,20.76 38.63,19.36 39.23,18.76 44.12,18.76 45.16,17.72 48.97,17.72 52.39,14.3 52.93,14.3 53.61,13.62 53.61,12.53 54.75,11.39 54.75,9.31 59.1,4.95 61.85,4.95 63.71,3.09 76.68,3.09 77.17,3.59 77.22,3.63 81.86,3.63 82.35,4.12 90.32,4.12 91.1,4.9 101.57,4.9 103.34,6.67 103.34,11.24 104.03,11.93 104.03,13.03 102.32,14.73 97.78,14.73 95.3,17.21 95.3,17.63 95.64,17.97 96.65,17.97 97.3,18.61 97.3,19.63 96.41,20.52 95.02,20.52 92.75,22.78 92.75,25.05 90.18,27.61 89.55,27.61 89.16,28 87.57,28 87.08,28.5 87.08,28.82 84.11,31.79 v2(84.11,34.9)
  BOTTOM w0.14: v2(84.11,34.9) 84.08,34.87 82.84,34.87 82.68,35.03 82.08,35.03 82.08,35.03 80.95,35.03 80.95,35.03 80.35,35.03 U26.A12
JTAG_TDI: length 116.1
  LY3_SIG1 w0.127: v1(101.99,7.18) 101.36,6.55 94.63,6.55 94.13,7.05 83.62,7.05 81.37,4.8 76.58,4.8 76.05,4.26 64.19,4.26 61.7,6.75 60.24,6.75 57.73,9.26 57.73,9.43 56.35,10.82 56.35,14.39 53.77,16.97 53.07,16.97 53,16.89 51.45,16.89 48.67,19.67 47.56,19.67 47.23,19.34 v1(45.4,19.34)
  LY6_SIG2 w0.127: v1(101.99,7.18) 103.82,9.01 103.82,13.27 101.89,15.21 98.88,15.21 97.88,16.2 97.68,16.2 97.22,16.66 97.22,17.67 96.92,17.96 96.92,18.82 97.22,19.12 97.22,21.02 96.73,21.51 95.4,21.51 94.23,22.68 94.23,24.12 88.52,29.83 87.51,29.83 86.87,30.46 86.87,31.7 85.18,33.39 84.59,33.39 84.3,33.67 84.3,34.11 83.93,34.48 83.93,34.48 83.78,34.63 v2(82.25,34.63)
  BOTTOM w0.14: J12.3 102.44,6.74 v1(101.99,7.18) ; v2(82.25,34.63) 79.95,34.63 U26.B11 ; R227.1 v1(45.4,19.34)
JTAG_TDO: length 174.8
  TOP w0.14: v2(83.57,34.09) 84.24,33.42 86.92,33.42 87.11,33.61 87.61,33.61 88.68,34.68 91.98,34.68 97.16,29.5 97.16,29.09 98.98,27.27 98.98,26.82 98.98,25.76 99.56,25.18 99.56,21.94 98.13,20.51 95.83,20.51 95.8,20.53 94.12,20.53 93.73,20.14 92.59,20.14 91.06,18.6 91.06,17.45 87.99,14.37 87.99,13.99 87.62,13.63 87.62,12.78 88.22,12.19 89.43,12.19 92.6,9.02 92.6,8.33 94.25,6.68 96.74,6.68 v1(97.37,7.31)
  LY3_SIG1 w0.127: v1(44.25,19.34) 45.37,18.22 49.18,18.22 52.28,15.13 53.36,15.13 54.12,14.37 54.12,12.74 55.26,11.6 55.26,11.18 55.26,10.18 55.84,9.61 55.95,9.61 56.9,8.66 56.9,7.88 58.81,5.96 61.56,5.96 63.92,3.6 76.47,3.6 76.96,4.1 76.96,4.1 77.01,4.14 81.65,4.14 82.14,4.63 85.54,4.63 86.37,5.47 87.64,5.47 88.44,4.67 90.16,4.67 90.95,5.47 101.42,5.47 102.83,6.88 102.83,11.45 103.52,12.14 103.52,12.77 102.07,14.22 97.57,14.22 94.79,17 94.79,17.85 95.43,18.48 95.69,18.48 95.95,18.74 95.95,19.58 95.52,20.01 94.81,20.01 94.21,20.61 92.24,22.57 92.24,24.84 89.97,27.11 89.34,27.11 88.95,27.5 87.36,27.5 86.57,28.29 86.57,28.61 83.57,31.6 v2(83.57,34.09)
  BOTTOM w0.14: v1(97.37,7.31) 98.01,6.68 98.88,6.68 99.9,5.66 J12.7 ; U26.A11 83.45,34.21 v2(83.57,34.09) ; R228.1 v1(44.25,19.34)
JTAG_TMS: length 159.5
  TOP w0.14: v1(42.64,25.19) 42.64,23.53 R79.1
  LY3_SIG1 w0.127: v2(79.14,34.61) 80.68,36.16 80.68,36.74 81.34,37.4 82.97,37.4 83.53,36.84 83.53,36.63 83.53,36.21 84.77,34.97 84.77,34.77 85.03,34.51 85.26,34.51 86.94,32.82 86.94,30.39 87.61,29.72 88.88,29.72 89.95,28.65 90.59,28.65 93.76,25.47 93.76,24.61 93.76,23.21 94.89,22.08 105.44,22.08 107.63,19.9 107.63,19.46 105.93,17.77 105.93,10.78 105.55,10.4 v1(105.55,7.06) 106.19,6.42 106.19,3.63 105.16,2.6 96.85,2.6 95.45,1.21 59.53,1.21 57.42,3.32 55.72,3.32 52.11,6.93 52.11,11.16 50.53,12.73 50.53,12.75 50.53,12.96 49.45,14.05 48.32,14.05 47.79,14.58 44.75,14.58 44.45,14.88 37.87,14.88 36.36,16.39 36.36,16.81 36.66,17.11 37.24,17.11 37.64,16.71 38.06,16.71 38.48,17.13 38.48,18.79 38.12,19.15 38.12,20.97 39.18,22.03 41.04,22.03 42.64,23.63 v1(42.64,25.19)
  BOTTOM w0.14: U26.C11 78.74,34.21 v2(79.14,34.61) ; v1(105.55,7.06) 104.74,7.06 104.05,6.36 104.04,6.36 103.78,6.1 103.78,6.1 103.71,6.03 J12.1
JTAG_TRSTN: length 121.9
  LY3_SIG1 w0.127: v1(41.46,19.32) 41.92,19.79 44.44,19.79 44.89,19.34 44.89,19.22 45.21,18.9 47.25,18.9 47.69,19.34 48.53,19.34 52.41,15.46 53.49,15.46 53.83,15.13 54.52,14.43 54.52,12.8 55.59,11.74 55.59,11.11 57.4,9.3 57.4,8.25 58.48,7.18 58.86,7.18 59.71,6.32 61.67,6.32 64.05,3.93 76.32,3.93 76.85,4.47 81.51,4.47 82,4.96 85.4,4.96 86.54,6.1 90.95,6.1 91.07,5.98 101.42,5.98 102.5,7.06 102.5,12.01 v1(103.01,12.52)
  LY6_SIG2 w0.127: v2(82.25,33.81) 83.26,33.81 84.03,33.04 85.06,33.04 86.11,32 86.11,30.76 87.38,29.48 88.4,29.48 93.53,24.35 93.53,21.9 96.29,19.14 96.29,17.75 96.89,17.15 96.89,15.89 97.98,14.8 101.82,14.8 103.01,13.62 v1(103.01,12.52)
  BOTTOM w0.14: v2(82.25,33.81) 79.93,33.81 U26.B10 ; R235.1 103.01,13.48 v1(103.01,12.52) 103.71,11.82 J12.2 ; R229.1 v1(41.46,19.32)
KEYPAD_PWRA: length 41.1
  TOP w0.508: SW4.1 SW4.2 126.03,22.69 125.6,23.11 125.6,36.2 125.95,36.54 SW2.1 SW2.2 SW1.1 SW1.2 127.15,53.19 126.49,53.85 v1(126.49,53.97)
  BOTTOM w0.508: R115.2 126.75,53.72 v1(126.49,53.97)
LCD_BACKLIGHTEN: length 155.5
  TOP w0.14: v1(61.09,18.67) 60.67,19.09 57.32,19.09 57.03,19.39 52.16,19.39 51.19,18.41 49.86,18.41 48.26,16.82 45,16.82 43.84,15.67 39.53,15.67 38.41,16.78 38.41,20.14 36.58,21.97 31.39,21.97 29.36,24.01 29.36,24.78 28.78,25.36 28.78,26.75 25.03,30.5 25.03,35.14 25.17,35.28 25.17,36.84 24.45,37.56 23.36,37.56 22.8,38.12 21.66,38.12 21.36,38.41 21.36,40.2 21,40.57 21,42.78 Q1.G
  LY6_SIG2 w0.127: v1(61.09,18.67) 61.4,18.36 61.4,17.21 60.06,15.88 60.06,13.63 62.31,11.38 62.46,11.38 63.03,10.81 63.03,6.76 65.45,4.33 82.24,4.33 84.78,6.88 87.19,6.88 88.62,8.31 88.62,9.8 90.04,11.22 90.04,14.48 89.78,14.75 89.78,18.01 v1(89.42,18.36) 89.24,18.55 89.24,23.31 87.69,24.85 87.69,25.16 87.43,25.43 87.21,25.65 86.25,25.65 79.76,32.13 79.76,35.17 79.52,35.41 v2(79.14,35.41)
  BOTTOM w0.14: R219.2 99.19,24.06 99.19,21.79 97.29,19.89 94.33,19.89 93.82,19.37 90.97,19.37 90.49,18.89 89.95,18.89 v1(89.42,18.36) ; U26.C12 78.74,35.01 v2(79.14,35.41)
LCD_CAP_TOUCH_WAKE: length 94.6
  TOP w0.14: v1(105.8,48.59) 105.22,49.17 99.37,49.17 96.51,52.03 92.84,52.03 91.91,52.96 89.86,52.96 89.33,53.49 89.33,53.52 88.08,54.77 79.7,54.77 78.11,53.18 74.08,53.18 73.85,52.95 70.97,52.95 70.26,52.23 64.08,52.23 63.55,51.7 63.55,50.1 62,48.54 62,48.12 62.05,48.07 62.05,47.54 61.23,46.72 61.23,45.03 61.5,44.76 61.5,43.89 62.1,43.29 62.1,42.92 61.92,42.73 61.92,39.1 61.56,38.75 61.56,36.61 62.39,35.78 v2(62.39,35.54) 62.39,35.1 62.75,34.75 62.75,32.63 60.79,30.68 55.48,30.68 55.16,30.35 55.16,30 55.25,29.91 55.25,29.12 55.16,29.03 55.16,25.43 53.82,24.1 53.82,21.67 55,20.49 R84.2
  BOTTOM w0.102: 64.55,35.01 U26.V12
  BOTTOM w0.14: v1(105.8,48.59) 106.31,48.08 R128.2 ; v2(62.39,35.54) 62.89,35.54 63.51,34.91 64,34.91 64.1,35.01 64.55,35.01
LED+: length 6.8
  TOP w0.254: U7.9 30.32,40.45 30.43,40.34 ; J1.2 31.81,34.61 31.56,34.86
  TOP w0.508: 31.17,35.25 31.56,34.86 ; 30.43,40.34 30.9,39.87 30.9,38.24 C75.1
MMC1_CLK: length 62.7
  LY6_SIG2 w0.127: v1(16.72,35.26) 16.72,37.29 17.42,37.99 17.42,38.36 19.2,40.14 26.16,40.14 34.09,32.22 34.09,30.89 35.75,29.22 35.75,26 36.12,25.63 36.55,25.63 37.48,24.7 38.41,24.7 38.67,24.96 39.15,24.96 40.1,24 41.67,24 42.38,24.71 42.79,24.71 43.54,25.46 50.69,25.46 50.77,25.39 57.65,25.39 57.85,25.59 60.97,25.59 v1(61.82,24.74)
  BOTTOM w0.14: R184.1 v1(16.72,35.26) 16.9,35.07 A1.16 ; R220.1 61.65,25.48 61.82,25.31 v1(61.82,24.74)
MMC1_CMD: length 74.3
  TOP w0.14: R57.1 15.96,35.13 v1(15.9,35.08)
  LY6_SIG2 w0.127: v2(65.99,32.61) 65.99,28.09 65.36,27.45 65.36,25.75 64.81,25.21 64.14,25.21 62.17,23.24 61.48,23.24 61.29,23.43 58.15,23.43 58.1,23.48 57.73,23.48 57.55,23.3 50.56,23.3 50.46,23.41 49.44,23.41 48.92,23.93 48.55,23.93 48.29,23.67 47.18,23.67 46.91,23.94 44.51,23.94 43.74,23.16 36.89,23.16 34.67,25.38 34.67,27.76 33.93,28.5 33.93,28.96 33.67,29.22 33.21,29.22 32.46,29.97 30.48,31.95 30.48,34.35 28.62,36.21 22.3,36.21 21.93,35.84 21.93,34.23 21.81,34.11 21.22,34.11 20.97,34.36 20.97,35.63 20.84,35.76 20.39,35.76 19.56,34.92 18.83,34.92 18.23,35.52 17.72,35.52 16.94,34.75 16.23,34.75 v1(15.9,35.08)
  BOTTOM w0.14: v2(65.99,32.61) U26.V9 ; A1.15 v1(15.9,35.08)
MMC1_D0: length 73.6
  TOP w0.14: v1(17.9,35.08) 17.23,35.75 R58.1
  LY6_SIG2 w0.127: v2(67.15,30.68) 66.81,30.34 66.81,28.96 66.6,28.75 66.6,26.02 64.13,23.55 63.39,23.55 61.29,21.45 59.73,21.45 58.57,20.29 54.91,20.29 52.69,22.5 35.67,22.5 33.53,24.64 33.53,25.9 32.96,26.47 32.38,26.47 30.21,28.65 30.21,30.54 29.08,31.67 29.08,33.81 27.37,35.52 22.95,35.52 22.59,35.17 22.59,33.52 22.25,33.17 17.14,33.17 16.76,33.55 16.76,33.94 v1(17.9,35.08)
  BOTTOM w0.14: A1.17 v1(17.9,35.08) ; U26.U7 67.48,31.01 v2(67.15,30.68)
MMC1_D1: length 74.3
  LY6_SIG2 w0.127: v2(65.08,30.82) 65.37,30.53 65.37,30.06 65.02,29.72 65.02,29.08 65.41,28.7 65.41,28.04 65.02,27.65 65.02,26.51 64.51,26 64.49,26 61.98,23.49 61.83,23.49 61.46,23.87 61.46,24.35 60.78,25.03 60.41,25.03 59.83,24.45 57.91,24.45 57.65,24.19 57.65,23.98 57.38,23.7 57.01,23.7 56.67,24.04 56.67,24.47 56.28,24.85 51.54,24.85 51.26,24.57 44.17,24.57 43.66,24.07 42.45,24.07 41.88,23.49 37.23,23.49 36.71,24.02 35.1,25.63 35.1,29.15 33.17,31.08 33.17,32.42 28.24,37.35 24.76,37.35 23.67,38.43 21.86,38.43 21.41,37.98 21.41,36.98 21.16,36.73 20.22,36.73 19.56,37.39 18.08,37.39 17.65,36.96 17.65,36.2 17.91,35.94 18.83,35.94 v1(19.39,35.38)
  BOTTOM w0.14: R183.1 18.88,35.89 v1(19.39,35.38) 18.9,34.9 A1.18 ; v2(65.08,30.82) 65.28,31.01 U26.V7
